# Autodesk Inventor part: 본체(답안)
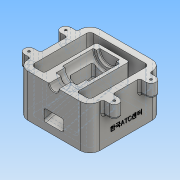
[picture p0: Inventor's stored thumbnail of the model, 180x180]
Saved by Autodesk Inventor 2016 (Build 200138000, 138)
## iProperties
Created: 2018-01
Part Number: 본체(답안)
Material: 알루미늄 6061
Document SubType Name: Modeling
Designer: Administrator
Density: 2.7 g/cm^3
Appearance: 알루미늄 - 평지
Mass: 995.217 g
Surface Area: 834.407 cm^2
Volume: 368.599 cm^3
Author: Administrator
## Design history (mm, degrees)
sketch "스케치1"
  geometry: L1 (-40, -55)-(40, -55); L2 (55, -40)-(55, 40); L3 (40, 55)-(-40, 55); L4 (-55, 40)-(-55, -40); L5 (-55, -55)-(55, 55); L6 (55, -55)-(-55, 55); L7 (-30, -45)-(30, -45); L8 (45, -30)-(45, 30); L9 (30, 45)-(-30, 45); L10 (-45, 30)-(-45, -30); L11 (-45, -45)-(45, 45); L12 (45, -45)-(-45, 45); A1 r 15 centre (-40, 40) between (-40, 55) and (-55, 40); A2 r 15 centre (-30, 30) between (-30, 45) and (-45, 30); A3 r 15 centre (40, 40) between (55, 40) and (40, 55); A4 r 15 centre (30, 30) between (45, 30) and (30, 45); A5 r 15 centre (30, -30) between (30, -45) and (45, -30); A6 r 15 centre (40, -40) between (40, -55) and (55, -40); A7 r 15 centre (-40, -40) between (-55, -40) and (-40, -55); A8 r 15 centre (-30, -30) between (-45, -30) and (-30, -45); 2 further points
  constraints: 24 end point, 16 point on circle, 16 point on line, 16 tangent, 8 centre point, 7 equal radius, 5 midpoint, 4 parallel, 2 horizontal, 2 perpendicular
  dimensions: "d6" = 110 distance of L6.end L5.end; "d7" = 110 distance of L5.end L6.start; "d8" = 90 distance of L12.end L11.end; "d9" = 90 distance of L11.end L12.start; "d10" = 15 radius of A1
extrude "돌출1" new body sketch "스케치1" distance "d11" = 65; taper "d12" = 0 deg
sketch "스케치2"
  geometry: L1 (-55, 0)-(-55, 65) reference; L2 (-55, 57.5)-(-36, 57.5); L3 (-36, 57.5)-(-36, 49); L4 (-40, 0)-(-40, 65) reference; L5 (-36, 49)-(-22, 49); L6 (-22, 49)-(-22, 45); L7 (-22, 45)-(25, 45); L8 (25, 45)-(25, 50); L9 (25, 50)-(30, 50); L10 (30, 50)-(30, 65); L11 (-55, 65)-(65.043, 65); 1 further point
  constraints: 18 end point, 4 perpendicular, 2 horizontal, 2 point on line, 2 vertical, 1 parallel
  dimensions: "d18" = 19 distance of L2.start L2.end; "d19" = 14 distance of L3.end L5.end; "d20" = 47 distance of L6.end L7.end; "d21" = 5 distance of L8.end L9.end; "d22" = 15 diameter of L2 L11; "d23" = 32 diameter of L5 L11; "d24" = 40 diameter of L7 L11; "d25" = 30 diameter of L9 L11
sketch "스케치3"
  geometry: L1 (-45, 8.564)-(35, 30); L2 (35, 30)-(35, 65); L3 (40, 65)-(-40, 65) reference; L4 (30, 0)-(-30, 0) reference; L5 (55, 0)-(55, 65) reference; L6 (-45, 0)-(-45, 65) reference; L7 (-45, 65)-(-30, 65) reference; L8 (-45, 8.564)-(-45, 65); L9 (35, 65)-(-30, 65) reference; L10 (-45, 65)-(35, 65); 1 further point
  constraints: 8 end point, 1 collinear, 1 perpendicular, 1 point on line, 1 vertical
  dimensions: "d13" = 30 distance from line of L4 L1.end; "d14" = 20 distance between parallel lines of L5 L2; "d15" = 105 deg angle of L6 L1
extrude "돌출2" join sketch "스케치3" stored distance "d16" = 50; taper "d17" = 0 deg
revolve "회전1" stored, may be unused: angle "d26" = 90 deg
sketch "스케치4"
  geometry: L1 (-55, 0)-(-55, 65) reference; L2 (-55, 11.061)-(20, 31.157); L3 (20, 31.157)-(20, 74.662); L4 (-22, 45)-(25, 45) reference; L5 (20, 74.662)-(-17, 74.662); L6 (-17, 74.662)-(-17, 39.243); L7 (-17, 39.243)-(-55, 29.061); L8 (-55, 29.061)-(-55, 11.061); L9 (35, 30)-(-45, 8.564) reference; 3 further points
  constraints: 12 end point, 3 perpendicular, 2 midpoint, 2 parallel, 2 point on line, 1 collinear, 1 vertical alignment
  dimensions: "d27" = 37 distance of L3.end L5.end; "d28" = 5 distance between parallel lines of L9 L2; "d29" = 18 distance of L7.end L2.start
extrude "돌출3" cut sketch "스케치4" stored distance "d30" = 30; taper "d31" = 0 deg
sketch "스케치5"
  geometry: L1 (-55, 40)-(-55, -40) reference; L2 (-55, 20.5)-(-65, 20.5); L3 (-65, 20.5)-(-65, 35.5); L4 (-65, 35.5)-(-55, 35.5); L5 (-55, 35.5)-(-55, 20.5); L6 (-55, 40)-(-55, 55); L7 (-55, 55)-(-40, 55); A1 r 15 centre (-40, 40) between (-40, 55) and (-55, 40) reference; A2 r 7.5 centre (-65, 28) between (-65, 35.5) and (-65, 20.5); 1 further point
  constraints: 12 end point, 2 parallel, 2 perpendicular, 2 point on circle, 2 point on line, 1 centre point, 1 horizontal, 1 midpoint, 1 tangent
  dimensions: "d32" = 27 vertical distance of L6.end A2.centre; "d33" = 10 distance from line of L1 A2.centre; "d34" = 7.5 radius of A2
extrude "돌출4" join sketch "스케치5" distance "d35" = 20; taper "d36" = 0 deg
sketch "스케치6"
  geometry: L1 (0, 80)-(0, 0) reference; L2 (0, -15)-(-65, -15) reference; 2 further points
  constraints: 1 other
  dimensions: "d37" = 55 distance from line of point (-20, 40) L2; "d38" = 20 distance from line of L1 point (-20, 40)
feature "엠보싱1" sketch "스케치6" dims "d6" = 110, "d7" = 110, "d8" = 90, "d9" = 90, "d10" = 15, "d39" = 0.5, "d40" = 0
fillet "모깎기1" dims "d41" = 1
fillet "모깎기2" dims "d42" = 3
chamfer "모따기1" distance "d43" = 1; stored, may be unused: second distance "d44" = 2, angle "d45" = 45 deg
hole "구멍1" diameter "d48" = 3.242; stored, may be unused: countersink angle "d52" = 90 deg, drill point angle "d54" = 118 deg; dims "d49" = 9, "d50" = 4, "d51" = 2, "d53" = 11, "d55" = 10, "d56" = 10
sketch "스케치7"
  geometry: L1 (-28, -45)-(-30, -45) reference; L2 (-29, -45)-(-45, -45); L3 (-45, -45)-(-45, -30); L4 (-45, -30)-(-29, -30); L5 (-29, -30)-(-29, -45); A1 r 15 centre (-30, -30) between (-45, -30) and (-30, -45) reference; 1 further point
  constraints: 8 end point, 2 parallel, 1 horizontal, 1 midpoint, 1 perpendicular
extrude "돌출5" cut sketch "스케치7" stored distance "d57" = 10; taper "d58" = 0 deg
fillet "모깎기3" dims "d59" = 5
node "솔리드1"
mirror "대칭1"
mirror "대칭2"
mirror "대칭3"
mirror "대칭4"
mirror "대칭5"
mirror "대칭6"
